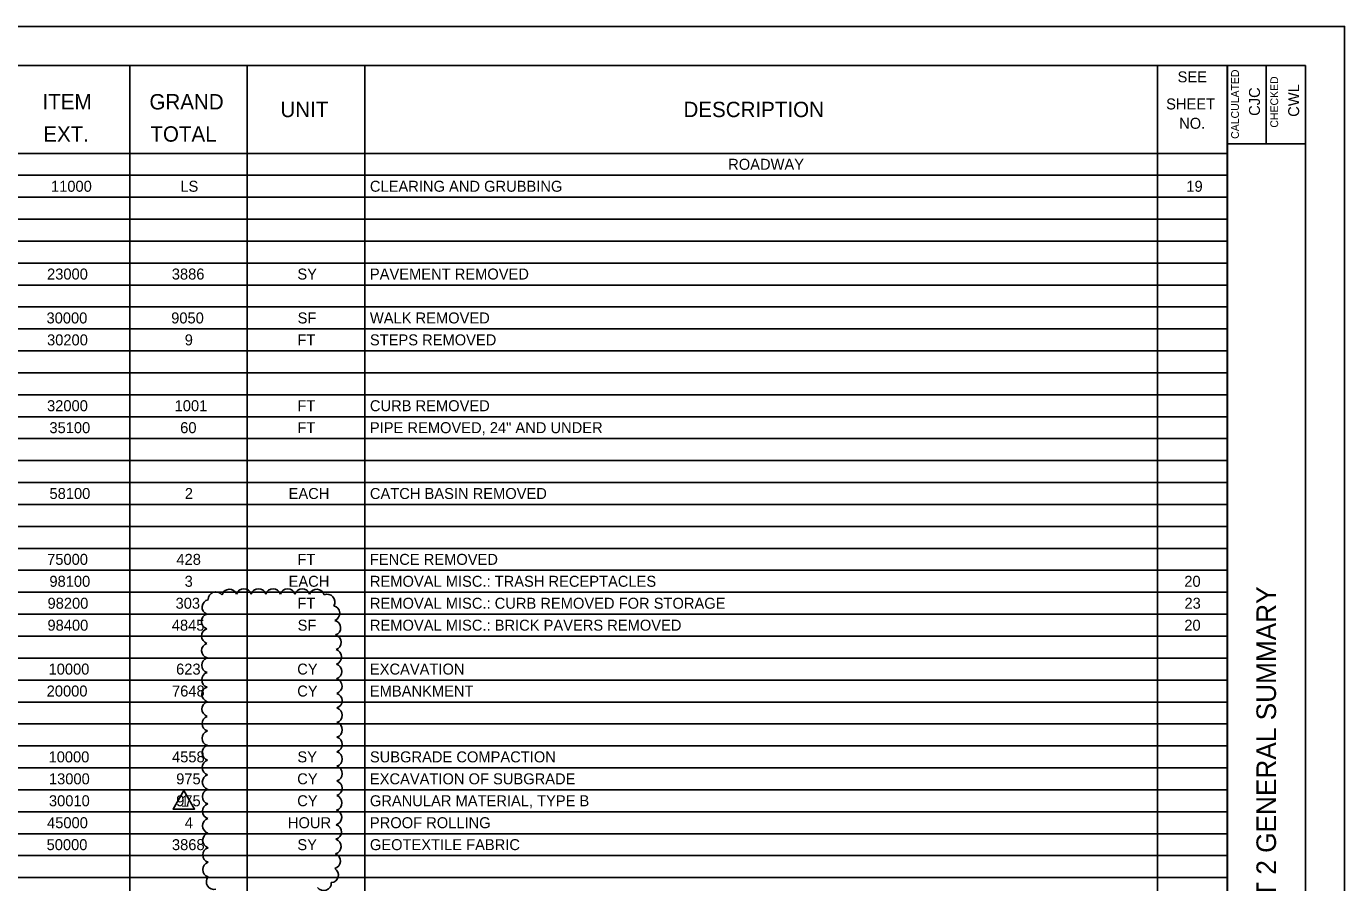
# Model space of a CAD drawing. Extents: x 0 to 34, y 0 to 22.
# Drawn here: x 17.19 to 34, y 11.08 to 22 of the extents above; entities that cross this region are included whole.
import ezdxf

# ---------------------------------------------------------------- set-up
doc = ezdxf.new("R2010")
doc.units = 0
for name, color, linetype in [('SH_Border', 7, 'Continuous'), ('SH_Cut_Line', 7, 'Continuous'), ('SH_Data', 7, 'Continuous'), ('SH_Text', 7, 'Continuous'), ('TX_P_1000', 7, 'Continuous')]:
    doc.layers.add(name, color=color, linetype=linetype)

msp = doc.modelspace()

# ---------------------------------------------------------------- linework, layer by layer
at = {"layer": 'SH_Border'}
for p, q in [((32.5, 0.5), (32.5, 21.5)), ((33, 21.5), (33, 20.5)), ((32.5, 20.5), (33.5, 20.5))]:
    msp.add_line(p, q, dxfattribs=at)
msp.add_lwpolyline([(2, 21.5), (33.5, 21.5), (33.5, 0.5), (2, 0.5)], close=True, dxfattribs=at)
at = {"layer": 'SH_Cut_Line'}
msp.add_lwpolyline([(0, 0), (34, 0), (34, 22), (0, 22)], close=True, dxfattribs=at)
at = {"layer": 'SH_Data'}
for p, q in [((15.72, 21.5), (32.504, 21.5)), ((18.504, 21.5), (18.504, 0.5)), ((20.002, 21.5), (20.002, 0.5)), ((21.501, 21.5), (21.501, 0.5)), ((31.614, 21.5), (31.614, 0.5)), ((32.504, 21.5), (32.504, 0.5)), ((2, 20.38), (32.504, 20.38)), ((2, 20.1), (32.504, 20.1)), ((2, 19.82), (32.504, 19.82)), ((2, 19.54), (32.504, 19.54)), ((2, 19.26), (32.504, 19.26)), ((2, 18.98), (32.504, 18.98)), ((2, 18.7), (32.504, 18.7)), ((2, 18.42), (32.504, 18.42)), ((2, 18.14), (32.504, 18.14)), ((2, 17.86), (32.504, 17.86)), ((2, 17.58), (32.504, 17.58)), ((2, 17.3), (32.504, 17.3)), ((2, 17.02), (32.504, 17.02)), ((2, 16.74), (32.504, 16.74)), ((2, 16.46), (32.504, 16.46)), ((2, 16.18), (32.504, 16.18)), ((2, 15.9), (32.504, 15.9)), ((2, 15.62), (32.504, 15.62)), ((2, 15.34), (32.504, 15.34)), ((2, 15.06), (32.504, 15.06)), ((2, 14.78), (32.504, 14.78)), ((2, 14.5), (32.504, 14.5)), ((2, 14.22), (32.504, 14.22)), ((2, 13.94), (32.504, 13.94)), ((2, 13.66), (32.504, 13.66)), ((2, 13.38), (32.504, 13.38)), ((2, 13.1), (32.504, 13.1)), ((2, 12.82), (32.504, 12.82)), ((2, 12.54), (32.504, 12.54)), ((2, 12.26), (32.504, 12.26)), ((2, 11.98), (32.504, 11.98)), ((2, 11.7), (32.504, 11.7)), ((2, 11.42), (32.504, 11.42)), ((2, 11.14), (32.504, 11.14))]:
    msp.add_line(p, q, dxfattribs=at)
at = {"layer": 'TX_P_1000'}
msp.add_lwpolyline([(19.194, 12.249), (19.057, 12.013), (19.33, 12.013)], close=True, dxfattribs=at)
for centre, radius, start, end in [((19.775, 14.722), 0.0976, 20.0252, 165.0252), ((19.96, 14.727), 0.0976, 18.0955, 163.0955), ((20.146, 14.728), 0.0976, 17.5007, 162.5007), ((20.332, 14.728), 0.0976, 17.5, 162.5), ((20.518, 14.728), 0.0976, 17.5, 162.5), ((20.704, 14.728), 0.0976, 17.4886, 162.4886), ((20.889, 14.722), 0.0976, 14.207, 159.207), ((19.524, 14.59), 0.0975, 101.8161, 246.8161), ((19.602, 14.689), 0.0977, 36.7231, 181.7231), ((21.023, 14.657), 0.0975, 328.8806, 113.8806), ((19.516, 14.408), 0.0976, 107.7774, 252.7774), ((21.085, 14.512), 0.0976, 292.072, 77.072), ((19.517, 14.221), 0.0976, 107.7971, 252.7971), ((21.096, 14.327), 0.0976, 290.1112, 75.1112), ((19.518, 14.035), 0.0976, 107.805, 252.805), ((21.103, 14.141), 0.0976, 289.2389, 74.2389), ((21.108, 13.955), 0.0976, 288.7142, 73.7142), ((19.519, 13.849), 0.0976, 107.8096, 252.8096), ((21.111, 13.769), 0.0976, 288.3537, 73.3537), ((19.52, 13.663), 0.0976, 107.8127, 252.8127), ((21.114, 13.583), 0.0976, 288.0863, 73.0863), ((19.521, 13.477), 0.0976, 107.815, 252.815), ((21.115, 13.397), 0.0976, 287.8778, 72.8778), ((19.522, 13.29), 0.0976, 107.8168, 252.8168), ((21.116, 13.211), 0.0976, 287.7092, 72.7092), ((19.523, 13.104), 0.0976, 107.8182, 252.8182), ((21.117, 13.025), 0.0976, 287.5693, 72.5693), ((19.524, 12.918), 0.0976, 107.8194, 252.8194), ((19.525, 12.732), 0.0976, 107.8202, 252.8202), ((21.117, 12.839), 0.0976, 287.4584, 72.4584), ((19.526, 12.545), 0.0976, 107.8202, 252.8202), ((21.116, 12.653), 0.0976, 287.3535, 72.3535), ((19.527, 12.359), 0.0976, 107.8202, 252.8202), ((21.116, 12.466), 0.0976, 287.2279, 72.2279), ((21.115, 12.28), 0.0976, 287.0737, 72.0737), ((19.528, 12.173), 0.0976, 107.8202, 252.8202), ((21.113, 12.094), 0.0976, 286.8782, 71.8782), ((19.529, 11.987), 0.0976, 107.8202, 252.8202), ((21.11, 11.908), 0.0976, 286.6187, 71.6187), ((19.53, 11.801), 0.0976, 107.8202, 252.8202), ((21.107, 11.722), 0.0976, 286.2502, 71.2502), ((19.531, 11.614), 0.0976, 107.8202, 252.8202), ((21.102, 11.536), 0.0976, 285.6646, 70.6646), ((19.532, 11.428), 0.0976, 107.8202, 252.8202), ((21.094, 11.351), 0.0976, 284.493, 69.493), ((19.533, 11.242), 0.0976, 107.8202, 252.8202), ((19.578, 11.085), 0.0976, 139.2641, 284.2641), ((21.068, 11.173), 0.0976, 273.9501, 58.9501), ((20.977, 11.072), 0.0977, 217.3339, 2.3339)]:
    msp.add_arc(centre, radius, start, end, dxfattribs=at)

# ---------------------------------------------------------------- texts
at = {"layer": 'SH_Data'}
for s, height, p in [('CALCULATED', 0.1, (32.652, 20.565)), ('CHECKED', 0.1, (33.152, 20.708)), ('CJC', 0.14, (32.92, 20.858)), ('CWL', 0.14, (33.42, 20.846)), ('4H PART 2 GENERAL SUMMARY', 0.25, (33.125, 9.672))]:
    msp.add_text(s, height=height, rotation=90, dxfattribs=at).set_placement(p)
at = {"layer": 'SH_Text'}
for s, height, p in [('SEE', 0.14, (31.869, 21.286)), ('ITEM', 0.196, (17.391, 20.94)), ('GRAND', 0.196, (18.755, 20.94)), ('UNIT', 0.196, (20.426, 20.842)), ('DESCRIPTION', 0.196, (25.567, 20.842)), ('SHEET', 0.14, (31.723, 20.94)), ('EXT.', 0.196, (17.401, 20.529)), ('TOTAL', 0.196, (18.767, 20.529)), ('NO.', 0.14, (31.889, 20.693)), ('ROADWAY', 0.14, (26.137, 20.17)), ('11000', 0.14, (17.499, 19.89)), ('LS', 0.14, (19.149, 19.89)), ('CLEARING AND GRUBBING', 0.14, (21.567, 19.89)), ('19', 0.14, (31.981, 19.89)), ('23000', 0.14, (17.449, 18.77)), ('3886', 0.14, (19.04, 18.77)), ('SY', 0.14, (20.642, 18.77)), ('PAVEMENT REMOVED', 0.14, (21.567, 18.77)), ('30000', 0.14, (17.442, 18.21)), ('9050', 0.14, (19.032, 18.21)), ('SF', 0.14, (20.645, 18.21)), ('WALK REMOVED', 0.14, (21.567, 18.21)), ('30200', 0.14, (17.449, 17.93)), ('9', 0.14, (19.205, 17.93)), ('FT', 0.14, (20.642, 17.93)), ('STEPS REMOVED', 0.14, (21.567, 17.93)), ('32000', 0.14, (17.449, 17.09)), ('1001', 0.14, (19.076, 17.09)), ('FT', 0.14, (20.642, 17.09)), ('CURB REMOVED', 0.14, (21.567, 17.09)), ('35100', 0.14, (17.479, 16.81)), ('60', 0.14, (19.147, 16.81)), ('FT', 0.14, (20.642, 16.81)), ('PIPE REMOVED, 24" AND UNDER', 0.14, (21.567, 16.81)), ('58100', 0.14, (17.48, 15.97)), ('2', 0.14, (19.206, 15.97)), ('EACH', 0.14, (20.53, 15.97)), ('CATCH BASIN REMOVED', 0.14, (21.567, 15.97)), ('75000', 0.14, (17.45, 15.13)), ('428', 0.14, (19.099, 15.13)), ('FT', 0.14, (20.642, 15.13)), ('FENCE REMOVED', 0.14, (21.567, 15.13)), ('98100', 0.14, (17.479, 14.85)), ('3', 0.14, (19.204, 14.85)), ('EACH', 0.14, (20.53, 14.85)), ('REMOVAL MISC.: TRASH RECEPTACLES', 0.14, (21.567, 14.85)), ('20', 0.14, (31.955, 14.85)), ('98200', 0.14, (17.455, 14.57)), ('303', 0.14, (19.088, 14.57)), ('FT', 0.14, (20.642, 14.57)), ('REMOVAL MISC.: CURB REMOVED FOR STORAGE', 0.14, (21.567, 14.57)), ('23', 0.14, (31.957, 14.57)), ('98400', 0.14, (17.454, 14.29)), ('4845', 0.14, (19.04, 14.29)), ('SF', 0.14, (20.645, 14.29)), ('REMOVAL MISC.: BRICK PAVERS REMOVED ', 0.14, (21.567, 14.29)), ('20', 0.14, (31.955, 14.29)), ('10000', 0.14, (17.468, 13.73)), ('623', 0.14, (19.095, 13.73)), ('CY', 0.14, (20.64, 13.73)), ('EXCAVATION', 0.14, (21.567, 13.73)), ('20000', 0.14, (17.444, 13.45)), ('7648', 0.14, (19.043, 13.45)), ('CY', 0.14, (20.64, 13.45)), ('EMBANKMENT', 0.14, (21.567, 13.45)), ('10000', 0.14, (17.468, 12.61)), ('4558', 0.14, (19.043, 12.61)), ('SY', 0.14, (20.642, 12.61)), ('SUBGRADE COMPACTION', 0.14, (21.567, 12.61)), ('13000', 0.14, (17.473, 12.33)), ('975', 0.14, (19.096, 12.33)), ('CY', 0.14, (20.64, 12.33)), ('EXCAVATION OF SUBGRADE', 0.14, (21.567, 12.33)), ('30010', 0.14, (17.473, 12.05)), ('975', 0.14, (19.096, 12.05)), ('CY', 0.14, (20.64, 12.05)), ('GRANULAR MATERIAL, TYPE B', 0.14, (21.567, 12.05)), ('45000', 0.14, (17.449, 11.77)), ('4', 0.14, (19.206, 11.77)), ('HOUR', 0.14, (20.521, 11.77)), ('PROOF ROLLING', 0.14, (21.567, 11.77)), ('50000', 0.14, (17.443, 11.49)), ('3868', 0.14, (19.042, 11.49)), ('SY', 0.14, (20.642, 11.49)), ('GEOTEXTILE FABRIC', 0.14, (21.567, 11.49))]:
    msp.add_text(s, height=height, dxfattribs=at).set_placement(p)
at = {"layer": 'TX_P_1000'}
msp.add_text('1', height=0.14, rotation=360, dxfattribs=at).set_placement((19.155, 12.043))

doc.saveas('drawing.dxf')
